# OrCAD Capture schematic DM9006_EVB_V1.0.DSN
size B; title: 2 Port Switch with uP Interface; rev: 1.0; note: DM9006 EVB BOARD
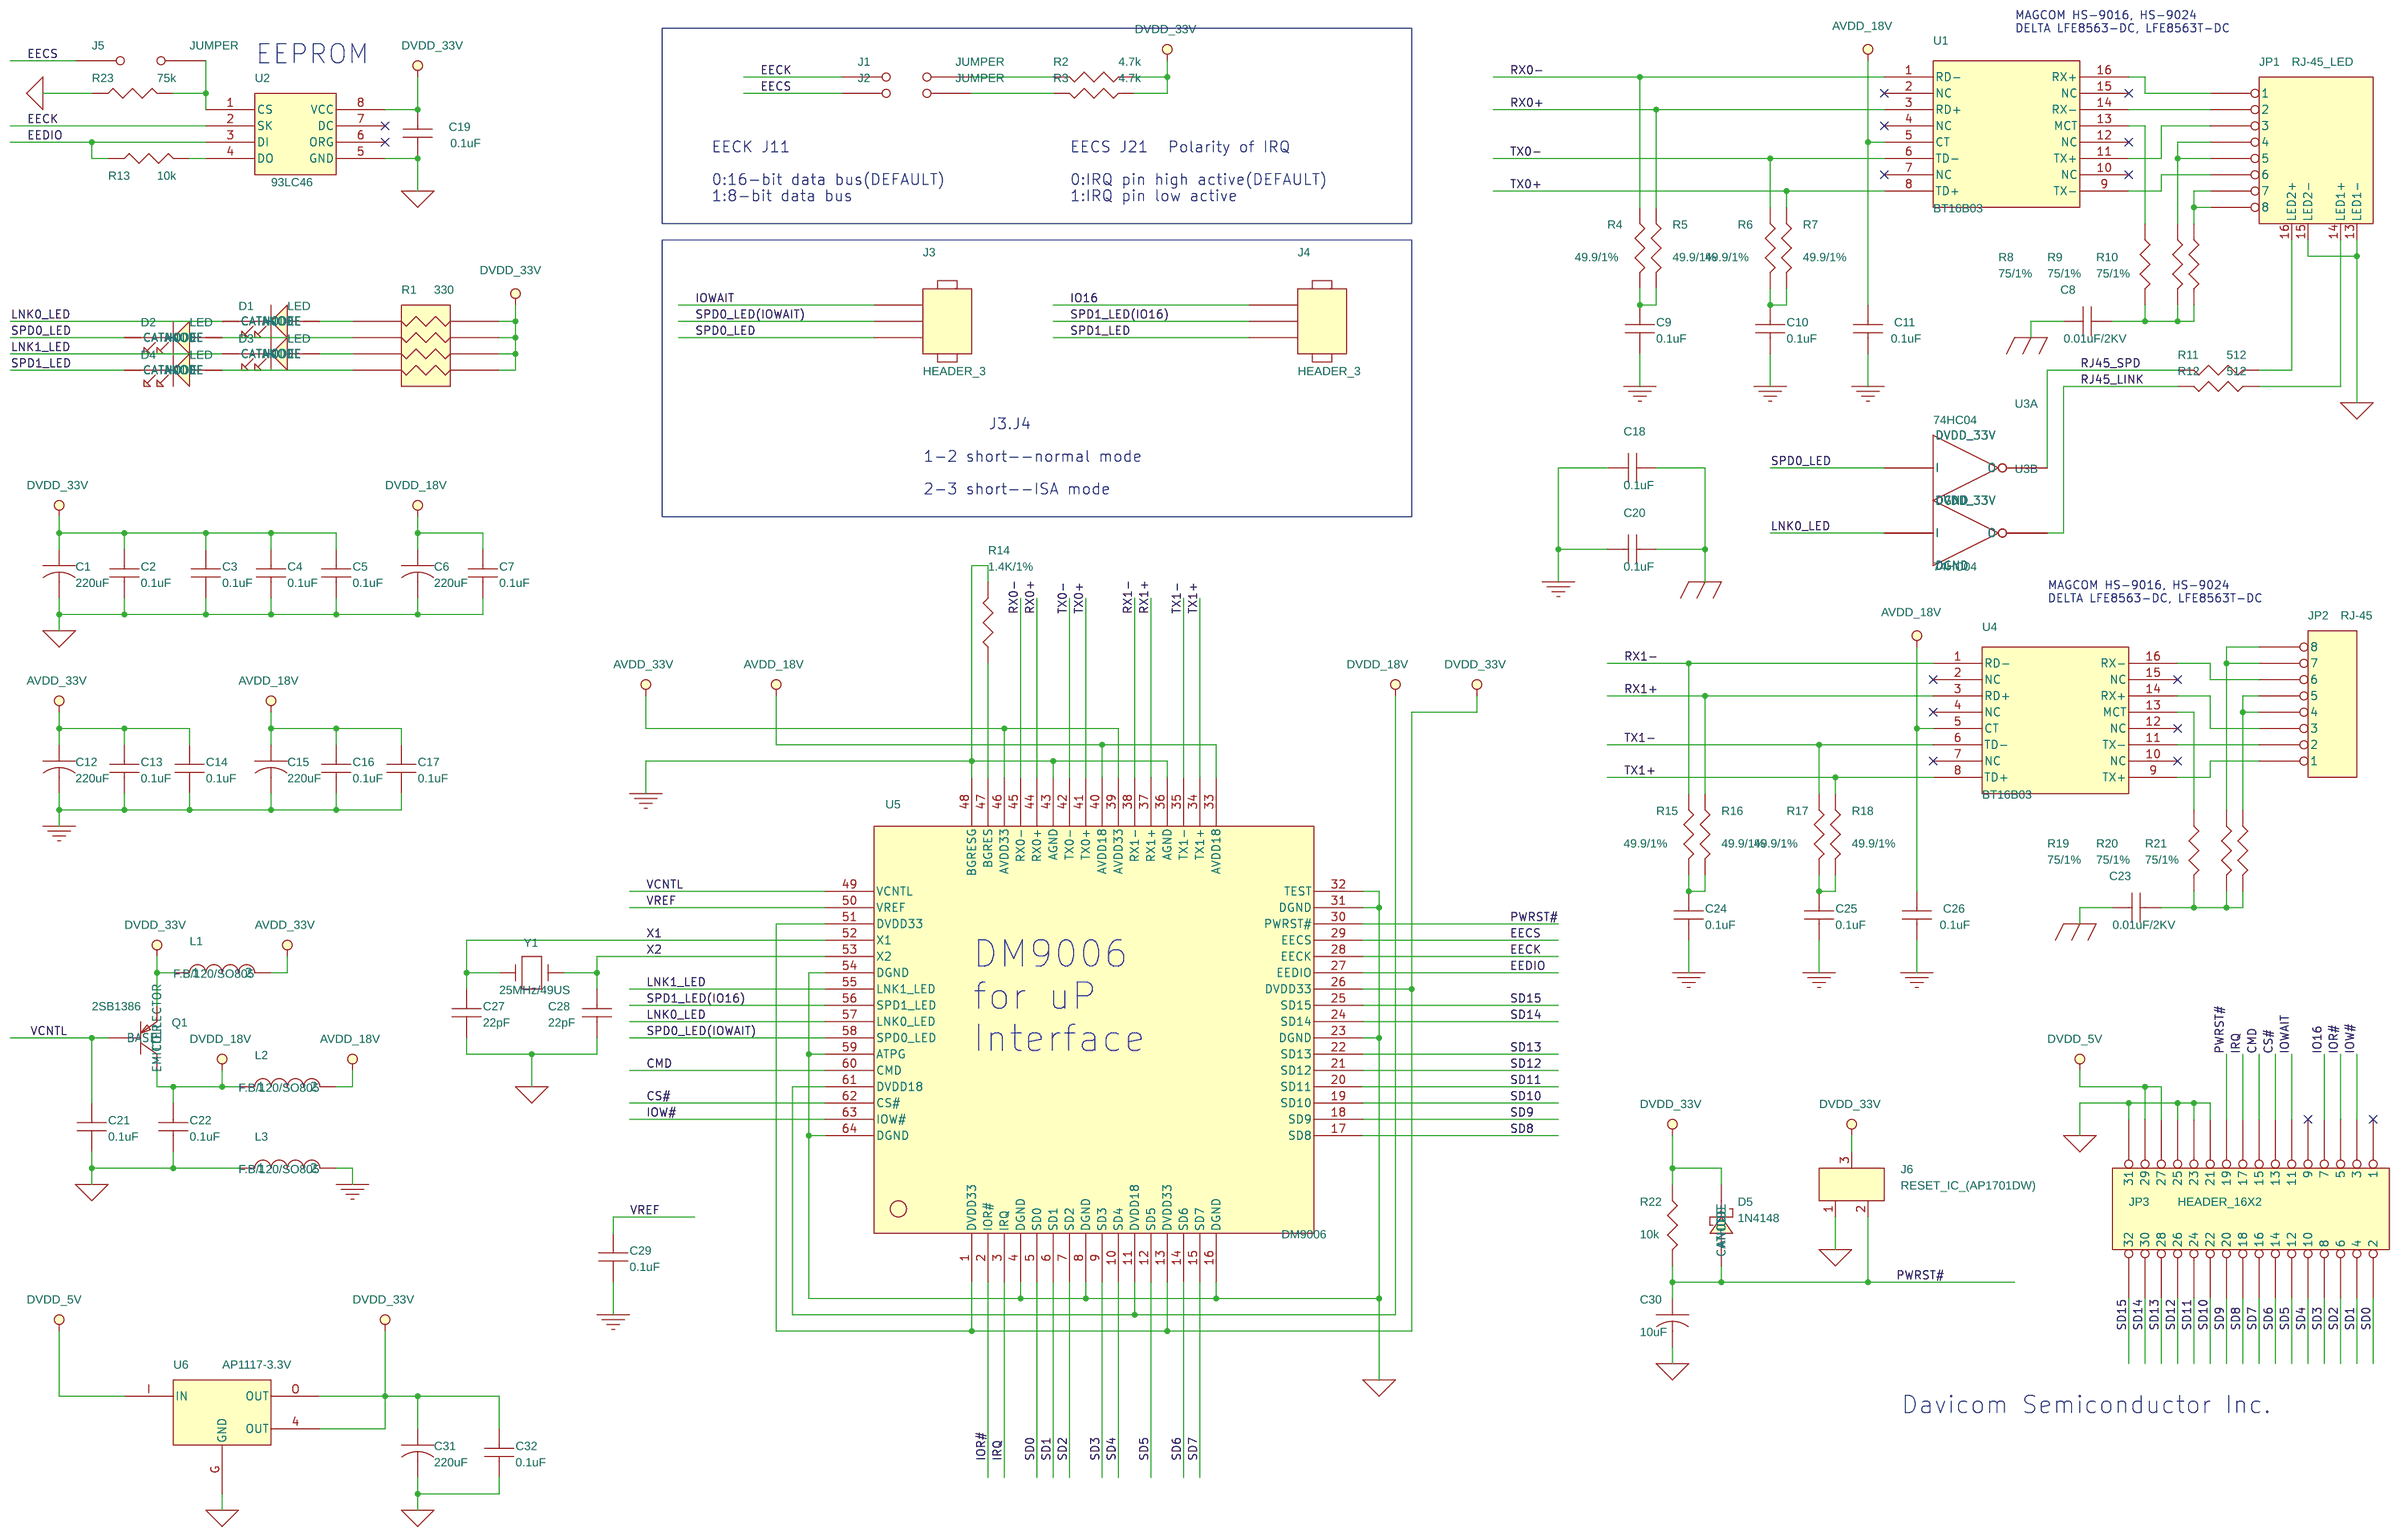
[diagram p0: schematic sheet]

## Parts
C1  220uF  [EC-MR05-2.5]
C2  0.1uF  [c0603]
C3  0.1uF  [c0603]
C4  0.1uF  [c0603]
C5  0.1uF  [c0603]
C6  220uF  [EC-MR05-2.5]
C7  0.1uF  [c0603]
C8  0.01uF/2KV  [C-10-03-7.5-5]
C9  0.1uF  [C0603]
C10  0.1uF  [C0603]
C11  0.1uF  [C0603]
C12  220uF  [EC-MR05-2.5]
C13  0.1uF  [c0603]
C14  0.1uF  [c0603]
C15  220uF  [EC-MR05-2.5]
C16  0.1uF  [c0603]
C17  0.1uF  [c0603]
C18  0.1uF  [C0603]
C19  0.1uF  [c0603]
C20  0.1uF  [C0603]
C21  0.1uF  [c0603]
C22  0.1uF  [c0603]
C23  0.01uF/2KV  [C-10-03-7.5-5]
C24  0.1uF  [C0603]
C25  0.1uF  [C0603]
C26  0.1uF  [C0603]
C27  22pF  [c0603]
C28  22pF  [c0603]
C29  0.1uF  [c0603]
C30  10uF  [EC-MR05-2.5]
C31  220uF  [EC-MR05-2.5]
C32  0.1uF  [c0603]
D1  LED  [LED]
D2  LED  [LED]
D3  LED  [LED]
D4  LED  [LED]
D5  1N4148  [SOD-80]
J1  JUMPER  [SIP2-2.54]
J2  JUMPER  [SIP2-2.54]
J3  HEADER_3  [SIP3-2.54]
J4  HEADER_3  [SIP3-2.54]
J5  JUMPER  [SIP2-2.54]
J6  RESET_IC_(AP1701DW)  [SOT23-213]
JP1  RJ-45_LED  [PJ-L1-FNN6]
JP2  RJ-45  [RJ45]
JP3  HEADER_16X2  [CON16X2-2.54A]
L1  F.B/120/SO805  [L0805]
L2  F.B/120/SO805  [L0805]
L3  F.B/120/SO805  [L0805]
Q1  2SB1386  [SC62]
R1  330  [8p4r-a1]
R2  4.7k  [R0603]
R3  4.7k  [R0603]
R4  49.9/1%  [R0603]
R5  49.9/1%  [R0603]
R6  49.9/1%  [R0603]
R7  49.9/1%  [R0603]
R8  75/1%  [R0603]
R9  75/1%  [R0603]
R10  75/1%  [R0603]
R11  512  [R0603]
R12  512  [R0603]
R13  10k  [R0603]
R14  1.4K/1%  [R0603]
R15  49.9/1%  [R0603]
R16  49.9/1%  [R0603]
R17  49.9/1%  [R0603]
R18  49.9/1%  [R0603]
R19  75/1%  [R0603]
R20  75/1%  [R0603]
R21  75/1%  [R0603]
R22  10k  [R0603]
R23  75k  [R0603]
U1  BT16B03  [PH163539]
U2  93LC46  [DIP8]
U3  74HC04  [SO14-6-1.27]  (sections A,B)
U4  BT16B03  [PH163539]
U5  DM9006  [LQFP64-1212-.5]
U6  AP1117-3.3V  [SOT223]
Y1  25MHz/49US  [49us]

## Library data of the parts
C1 C6 C12 C15 C30 C31 = C
C2-C5 C7 C9-C11 C13 C14 C16-C18 C20-C22 C24-C26 C29 = CAP_NP
C8 C23 = CAP_NP: 1ST PART FIELD: CE
C19 C27 C28 C32 = CAPACITOR_NON-POL
D1-D4 = LED_0
D5 = DIODE_SCHOTTKY_0
J1 J2 J5 = JUMPER
J3 J4 = HEADER_3
J6 = CON3_1
JP1 = HEADER_8_0: 1ST PART FIELD: RJ8-45
JP2 = HEADER_8: 1ST PART FIELD: RJ8-45
JP3 = HEADER_16X2
L1 = INDUCTOR_1
L2 = INDUCTOR_2
L3 = INDUCTOR
Q1 = PNP_0
R1 = RESISTOR_DIP_4
R2-R23 = R
U1 = MIM_6: 1ST PART FIELD: YCL0303
U2 = 93C46_2
U3 = 7404_2
U4 = MIM_5: 1ST PART FIELD: YCL0303
U5 = DM9013E_1
U6 = 1117-3_1.3
Y1 = CRYSTAL_0

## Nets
AGND: C9.2 C10.2 C11.2 C12.2 C13.2 C14.2 C15.2 C16.2 C17.2 C18.2 C20.2 C24.2 C25.2 C26.2 C29.2 L3.2 R14.2 U5.36(AGND) U5.43(AGND) U5.48(BGRESG)
AVDD_18V: C11.1 C15.1 C16.1 C17.1 C26.1 L2.2 U1.5(CT) U4.5(CT) U5.33(AVDD18) U5.40(AVDD18)
AVDD_33V: C12.1 C13.1 C14.1 L1.2 U5.39(AVDD33) U5.46(AVDD33)
DGND: C1.2 C2.2 C3.2 C4.2 C5.2 C6.2 C7.2 C19.2 C21.2 C22.2 C27.2 C28.2 C30.2 C31.2 C32.2 J6.1 JP1.13(LED1-) JP1.15(LED2-) JP3.21 JP3.23 JP3.25 JP3.31 L3.1 R23.1 U2.5(GND) U3.7(DGND) U5.4(DGND) U5.8(DGND) U5.16(DGND) U5.23(DGND) U5.31(DGND) U5.32(TEST) U5.54(DGND) U5.59(ATPG) U5.64(DGND) U6.G(GND)
DVDD_5V: JP3.27 JP3.29 U6.I(IN)
DVDD_18V: C6.1 C7.1 C22.1 L2.1 Q1.C(COLLECTOR) U5.11(DVDD18) U5.61(DVDD18)
DVDD_33V: C1.1 C2.1 C3.1 C4.1 C5.1 C19.1 C31.1 C32.1 D5.C(CATHODE) J6.3 L1.1 Q1.E(EMITTER) R1.5 R1.6 R1.7 R1.8 R2.1 R3.1 R22.1 U2.8(VCC) U3.14(DVDD_33V) U5.1(DVDD33) U5.13(DVDD33) U5.26(DVDD33) U5.51(DVDD33) U6.4(OUT) U6.O(OUT)
CHASIS_GND: C8.1 C18.1 C20.1 C23.1
CMD: JP3.15 U5.60(CMD)
CS#: JP3.13 U5.62(CS#)
EECK: J1.1 U2.2(SK) U5.28(EECK)
EECS: J2.1 J5.1 U5.29(EECS)
EEDIO: R13.1 U2.3(DI) U5.27(EEDIO)
IO16: J4.3 JP3.7
IOR#: JP3.5 U5.2(IOR#)
IOW#: JP3.3 U5.63(IOW#)
IOWAIT: J3.3 JP3.11
IRQ: JP3.17 U5.3(IRQ)
LNK0_LED: D1.C(CATHODE) U3.3(I) U5.57(LNK0_LED)
LNK1_LED: D3.C(CATHODE) U5.55(LNK1_LED)
PWRST#: C30.1 D5.A(ANODE) J6.2 JP3.19 R22.2 U5.30(PWRST#)
RJ45_LINK: R12.2 U3.4(O)
RJ45_SPD: R11.2 U3.2(O)
RX0+: R5.1 U1.3(RD+) U5.44(RX0+)
RX0-: R4.1 U1.1(RD-) U5.45(RX0-)
RX1+: R16.1 U4.3(RD+) U5.37(RX1+)
RX1-: R15.1 U4.1(RD-) U5.38(RX1-)
SD0: JP3.2 U5.5(SD0)
SD1: JP3.4 U5.6(SD1)
SD2: JP3.6 U5.7(SD2)
SD3: JP3.8 U5.9(SD3)
SD4: JP3.10 U5.10(SD4)
SD5: JP3.12 U5.12(SD5)
SD6: JP3.14 U5.14(SD6)
SD7: JP3.16 U5.15(SD7)
SD8: JP3.18 U5.17(SD8)
SD9: JP3.20 U5.18(SD9)
SD10: JP3.22 U5.19(SD10)
SD11: JP3.24 U5.20(SD11)
SD12: JP3.26 U5.21(SD12)
SD13: JP3.28 U5.22(SD13)
SD14: JP3.30 U5.24(SD14)
SD15: JP3.32 U5.25(SD15)
SPD0_LED: D2.C(CATHODE) J3.1 U3.1(I)
SPD0_LED(IOWAIT): J3.2 U5.58(SPD0_LED)
SPD1_LED: D4.C(CATHODE) J4.1
SPD1_LED(IO16): J4.2 U5.56(SPD1_LED)
TX0+: R7.1 U1.8(TD+) U5.41(TX0+)
TX0-: R6.1 U1.6(TD-) U5.42(TX0-)
TX1+: R18.1 U4.8(TD+) U5.34(TX1+)
TX1-: R17.1 U4.6(TD-) U5.35(TX1-)
VCNTL: C21.1 Q1.B(BASE) U5.49(VCNTL)
VREF: C29.1 U5.50(VREF)
X1: C27.1 U5.52(X1) Y1.1
X2: C28.1 U5.53(X2) Y1.2
N16700762: J2.2 R3.2
N16700879: J1.2 R2.2
N16891330: R13.2 U2.4(DO)
N16918910: D2.A(ANODE) R1.3
N16918912: JP1.6 U1.9(TX-)
N16918923: JP2.7 JP2.8 R20.1
N16918925: C8.2 R8.2 R9.2 R10.2
N16918962: JP1.7 JP1.8 R10.1
N16918974: JP1.3 U1.11(TX+)
N16918976: JP2.3 U4.14(RX+)
N16918997: C23.2 R19.2 R20.2 R21.2
N16918999: JP2.1 U4.9(TX+)
N16919001: D3.A(ANODE) R1.2
N16919046: JP1.14(LED1+) R12.1
N16919097: JP1.4 JP1.5 R9.1
N16919121: JP2.4 JP2.5 R21.1
N16919137: JP1.16(LED2+) R11.1
N16919184: C10.1 R6.2 R7.2
N16919196: JP2.2 U4.11(TX-)
N16919203: JP2.6 U4.16(RX-)
N16919221: D1.A(ANODE) R1.4
N16919247: JP1.1 U1.16(RX+)
N16919288: JP1.2 U1.14(RX-)
N16919304: C24.1 R15.2 R16.2
N16919396: C9.1 R4.2 R5.2
N16919500: D4.A(ANODE) R1.1
N16919506: R8.1 U1.13(MCT)
N16919664: R19.1 U4.13(MCT)
N16919767: C25.1 R17.2 R18.2
N16931285: R14.1 U5.47(BGRES)
N16957529: J5.2 R23.2 U2.1(CS)

Not connected (* = marked no-connect by the designer): JP3 1* 9*; U1 2(NC)* 4(NC)* 7(NC)* 10(NC)* 12(NC)* 15(NC)*; U2 6(ORG)* 7(DC)*; U4 2(NC)* 4(NC)* 7(NC)* 10(NC)* 12(NC)* 15(NC)*

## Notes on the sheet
- MAGCOM HS-9016, HS-9024
  DELTA LFE8563-DC, LFE8563T-DC
- EEPROM
- EECK J11
- EECS J21
- Polarity of IRQ
- 0:16-bit data bus(DEFAULT)
- 1:8-bit data bus
- 0:IRQ pin high active(DEFAULT)
- 1:IRQ pin low active
- J3.J4
- 1-2 short--normal mode
- 2-3 short--ISA mode
- MAGCOM HS-9016, HS-9024
  DELTA LFE8563-DC, LFE8563T-DC
- DM9006
  for uP
  Interface
- Davicom Semiconductor Inc.
